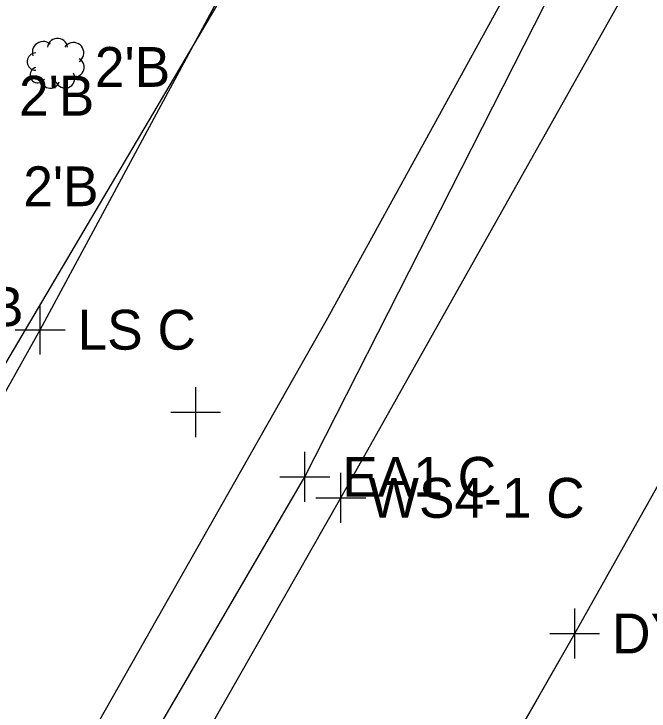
# Model space of a CAD drawing. Extents: x 1363693 to 1365209, y 422201 to 424153.
# Drawn here: x 1364115.18 to 1364140.7, y 422835.87 to 422863.86 of the extents above; entities that cross this region are included whole.
import ezdxf

# ---------------------------------------------------------------- set-up
doc = ezdxf.new("R2010")
doc.units = 0
for name, color, linetype in [('O-ALGN-BASELINE-WERK-CL-RW', 7, 'Continuous'), ('OWNERS', 7, 'Continuous'), ('PM_X_Channelizing_Line', 7, 'Continuous'), ('PM_X_CL_Double_Solid', 7, 'Continuous'), ('PM_X_Edge_Line', 7, 'Continuous'), ('SV_X_Original_Ground', 7, 'Continuous'), ('SV_X_Random_Point', 7, 'Continuous'), ('SV_X_Shot_Marker', 7, 'Continuous'), ('UT_X_FO', 7, 'Continuous'), ('UT_X_Gas', 7, 'Continuous'), ('VG_X_Cells', 7, 'Continuous'), ('VG_X_Flower_Bed', 7, 'Continuous'), ('VG_X_Text', 7, 'Continuous')]:
    doc.layers.add(name, color=color, linetype=linetype)

msp = doc.modelspace()

# ---------------------------------------------------------------- linework, layer by layer
at = {"layer": 'O-ALGN-BASELINE-WERK-CL-RW'}
msp.add_lwpolyline([(1364112.961, 422795.674), (1364125.29, 422817.23), (1364137.711, 422838.984), (1364149.842, 422860.568), (1364162.178, 422882.564), (1364162.178, 422882.564), (1364174.207, 422904.529), (1364174.207, 422904.529), (1364181.519, 422918.743), (1364181.519, 422918.743), (1364185.177, 422926.315), (1364185.177, 422926.315), (1364194.648, 422946.825), (1364194.648, 422946.825), (1364195.429, 422948.569), (1364195.429, 422948.569), (1364199.632, 422958.68), (1364199.632, 422958.68), (1364204.422, 422971.255), (1364204.422, 422971.255), (1364205.193, 422973.458), (1364205.193, 422973.458), (1364212.224, 422994.557)], dxfattribs=at)
at = {"layer": 'OWNERS'}
msp.add_lwpolyline([(1364089.632, 422780.271), (1364102.08, 422801.911), (1364114.271, 422823.678), (1364126.868, 422845.272), (1364138.192, 422867.568), (1364150.546, 422889.234), (1364150.546, 422889.234), (1364162.879, 422910.978), (1364162.879, 422910.978), (1364170.332, 422924.545), (1364170.332, 422924.545), (1364173.925, 422931.803), (1364173.925, 422931.803), (1364182.923, 422951.414), (1364182.923, 422951.414), (1364183.888, 422953.606), (1364183.888, 422953.606), (1364188.472, 422964.837), (1364188.472, 422964.837), (1364192.543, 422975.639), (1364192.543, 422975.639), (1364193.28, 422977.776), (1364193.28, 422977.776), (1364200.007, 422998.363)], dxfattribs=at)
at = {"layer": 'PM_X_Channelizing_Line'}
for p, q in [((1364128.313, 422844.429), (1364140.56, 422866.197)), ((1364137.711, 422838.984), (1364149.842, 422860.568)), ((1364115.929, 422822.695), (1364128.313, 422844.429)), ((1364125.29, 422817.23), (1364137.711, 422838.984))]:
    msp.add_line(p, q, dxfattribs=at)
at = {"layer": 'PM_X_CL_Double_Solid'}
for p, q in [((1364137.711, 422838.984), (1364149.842, 422860.568)), ((1364125.29, 422817.23), (1364137.711, 422838.984))]:
    msp.add_line(p, q, dxfattribs=at)
at = {"layer": 'PM_X_Edge_Line'}
for p, q in [((1364128.313, 422844.429), (1364140.56, 422866.197)), ((1364115.929, 422822.695), (1364128.313, 422844.429))]:
    msp.add_line(p, q, dxfattribs=at)
at = {"layer": 'SV_X_Original_Ground'}
for p, q in [((1364122.485, 422846.867), (1364122.485, 422848.867)), ((1364121.485, 422847.867), (1364123.485, 422847.867)), ((1364128.313, 422843.429), (1364128.313, 422845.429)), ((1364127.313, 422844.429), (1364129.313, 422844.429)), ((1364137.711, 422837.984), (1364137.711, 422839.984)), ((1364136.711, 422838.984), (1364138.711, 422838.984))]:
    msp.add_line(p, q, dxfattribs=at)
at = {"layer": 'SV_X_Random_Point'}
for p, q in [((1364116.235, 422850.18), (1364116.235, 422852.18)), ((1364115.235, 422851.18), (1364117.235, 422851.18))]:
    msp.add_line(p, q, dxfattribs=at)
at = {"layer": 'SV_X_Shot_Marker'}
for p, q in [((1364126.868, 422844.272), (1364126.868, 422846.272)), ((1364125.868, 422845.272), (1364127.868, 422845.272))]:
    msp.add_line(p, q, dxfattribs=at)
at = {"layer": 'UT_X_FO'}
msp.add_lwpolyline([(1364198.41, 423083.145), (1364202.916, 423079.215), (1364206.614, 423072.625), (1364206.927, 423065.384), (1364205.607, 423052.889), (1364202.652, 423033.176), (1364193.585, 423006.537), (1364182.955, 422981.103), (1364130.325, 422876.058), (1364040.63, 422724.214)], dxfattribs=at)
at = {"layer": 'UT_X_Gas'}
msp.add_lwpolyline([(1364207.557, 423089.372), (1364211.518, 423072.856), (1364208.943, 423046.381), (1364201.649, 423012.485), (1364191.712, 422981.617), (1364181.14, 422953.292), (1364166.466, 422921.961), (1364127.708, 422851.525), (1364051.86, 422717.903)], dxfattribs=at)
at = {"layer": 'VG_X_Cells'}
for points in [[(1364117.339, 422862.525), (1364117.32, 422862.6), (1364117.288, 422862.671), (1364117.243, 422862.735), (1364117.186, 422862.789), (1364117.121, 422862.831), (1364117.048, 422862.86), (1364116.972, 422862.875), (1364116.893, 422862.875), (1364116.817, 422862.86), (1364116.744, 422862.831), (1364116.679, 422862.789), (1364116.622, 422862.735), (1364116.577, 422862.671), (1364116.544, 422862.6), (1364116.526, 422862.525)], [(1364116.642, 422862.641), (1364116.577, 422862.69), (1364116.504, 422862.725), (1364116.425, 422862.747), (1364116.343, 422862.753), (1364116.262, 422862.743), (1364116.184, 422862.719), (1364116.113, 422862.68), (1364116.049, 422862.629), (1364115.997, 422862.566), (1364115.957, 422862.495), (1364115.931, 422862.418), (1364115.921, 422862.337), (1364115.926, 422862.255), (1364115.946, 422862.176)], [(1364117.803, 422861.944), (1364117.864, 422861.993), (1364117.914, 422862.052), (1364117.953, 422862.12), (1364117.978, 422862.194), (1364117.989, 422862.27), (1364117.986, 422862.348), (1364117.968, 422862.424), (1364117.937, 422862.495), (1364117.893, 422862.56), (1364117.838, 422862.615), (1364117.774, 422862.658), (1364117.703, 422862.69), (1364117.627, 422862.707), (1364117.549, 422862.71), (1364117.472, 422862.699), (1364117.399, 422862.674), (1364117.331, 422862.635), (1364117.272, 422862.585), (1364117.223, 422862.525)], [(1364116.062, 422862.292), (1364115.998, 422862.286), (1364115.936, 422862.269), (1364115.878, 422862.24), (1364115.827, 422862.201), (1364115.784, 422862.154), (1364115.75, 422862.099), (1364115.727, 422862.039), (1364115.715, 422861.976), (1364115.715, 422861.912), (1364115.727, 422861.849), (1364115.75, 422861.789), (1364115.784, 422861.734), (1364115.827, 422861.687), (1364115.878, 422861.648), (1364115.936, 422861.619), (1364115.998, 422861.602), (1364116.062, 422861.596)], [(1364117.455, 422861.363), (1364117.525, 422861.34), (1364117.599, 422861.33), (1364117.673, 422861.335), (1364117.745, 422861.353), (1364117.812, 422861.385), (1364117.871, 422861.429), (1364117.922, 422861.483), (1364117.961, 422861.546), (1364117.988, 422861.615), (1364118.001, 422861.688), (1364118, 422861.762), (1364117.985, 422861.835), (1364117.957, 422861.903), (1364117.916, 422861.965), (1364117.864, 422862.018), (1364117.803, 422862.06)], [(1364116.062, 422861.712), (1364116.004, 422861.691), (1364115.951, 422861.659), (1364115.906, 422861.617), (1364115.87, 422861.567), (1364115.844, 422861.512), (1364115.829, 422861.452), (1364115.827, 422861.391), (1364115.836, 422861.33), (1364115.857, 422861.272), (1364115.889, 422861.22), (1364115.931, 422861.174), (1364115.98, 422861.138), (1364116.036, 422861.112), (1364116.096, 422861.097), (1364116.157, 422861.094), (1364116.218, 422861.104), (1364116.276, 422861.125), (1364116.328, 422861.156), (1364116.374, 422861.198), (1364116.41, 422861.247)], [(1364116.874, 422861.131), (1364116.909, 422861.064), (1364116.957, 422861.004), (1364117.014, 422860.955), (1364117.081, 422860.918), (1364117.153, 422860.895), (1364117.228, 422860.886), (1364117.304, 422860.891), (1364117.377, 422860.912), (1364117.445, 422860.945), (1364117.505, 422860.992), (1364117.555, 422861.049), (1364117.593, 422861.115), (1364117.618, 422861.187), (1364117.628, 422861.262), (1364117.623, 422861.338), (1364117.604, 422861.411), (1364117.571, 422861.48)], [(1364116.294, 422861.247), (1364116.298, 422861.179), (1364116.315, 422861.113), (1364116.344, 422861.051), (1364116.384, 422860.995), (1364116.435, 422860.949), (1364116.493, 422860.913), (1364116.557, 422860.889), (1364116.625, 422860.878), (1364116.694, 422860.88), (1364116.76, 422860.895), (1364116.823, 422860.922), (1364116.879, 422860.961), (1364116.927, 422861.01), (1364116.965, 422861.068), (1364116.991, 422861.131)]]:
    msp.add_lwpolyline(points, dxfattribs=at)
at = {"layer": 'VG_X_Flower_Bed'}
for p, q in [((1364116.235, 422851.18), (1364128.07, 422873.145)), ((1364104.088, 422829.493), (1364116.235, 422851.18))]:
    msp.add_line(p, q, dxfattribs=at)

# ---------------------------------------------------------------- texts
at = {"layer": 'SV_X_Original_Ground'}
for s, p in [('WS4-1 C', (1364129.432, 422843.629)), ('DYS C CR1 C', (1364139.211, 422838.184))]:
    msp.add_text(s, height=1.6, dxfattribs=at).set_placement(p)
at = {"layer": 'SV_X_Random_Point'}
msp.add_text('LS C', height=1.6, dxfattribs=at).set_placement((1364117.735, 422850.38))
at = {"layer": 'SV_X_Shot_Marker'}
msp.add_text('EA1 C', height=1.6, dxfattribs=at).set_placement((1364128.368, 422844.472))
at = {"layer": 'VG_X_Text'}
for p in [(1364118.432, 422860.931), (1364115.385, 422859.775), (1364115.557, 422856.14), (1364112.545, 422851.305)]:
    msp.add_text("2'B", height=1.6, dxfattribs=at).set_placement(p)

doc.saveas('drawing.dxf')
